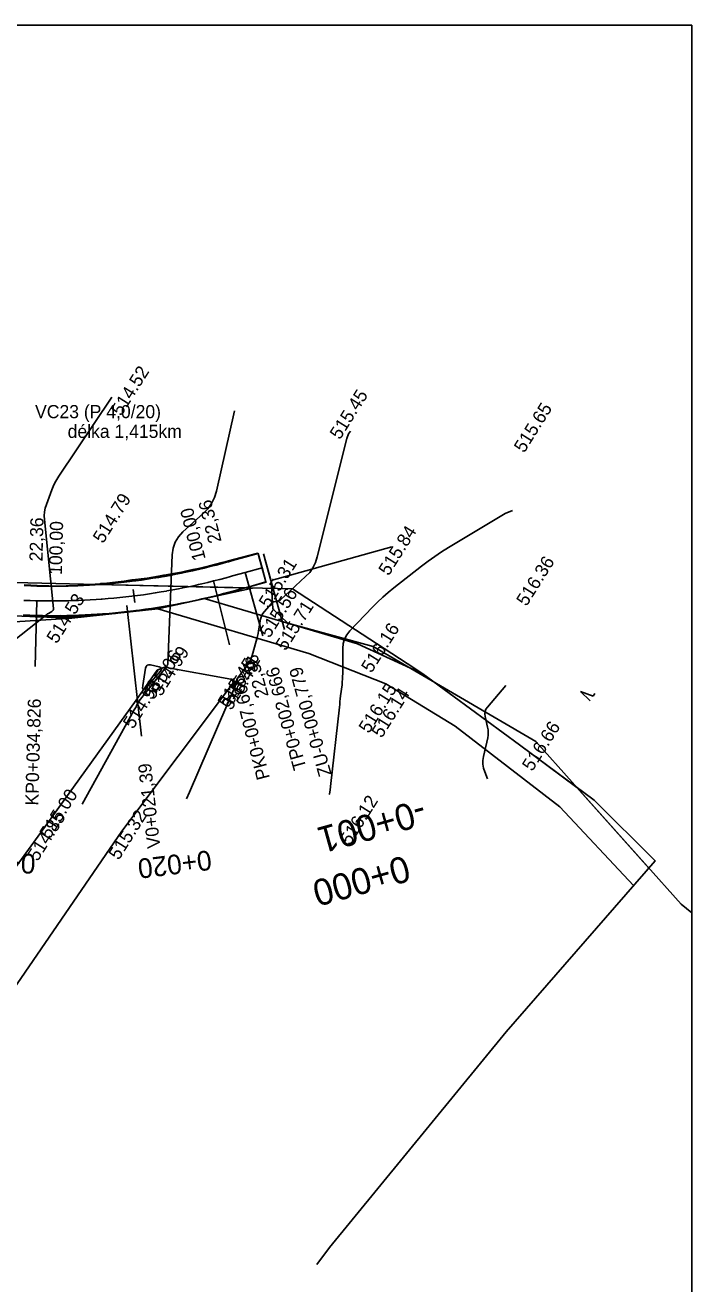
# Model space of a CAD drawing. Extents: x -636600 to -628587, y -1090963 to -1085869.
# Drawn here: x -629108.8 to -629007.3, y -1090119.5 to -1089927.9 of the extents above; entities that cross this region are included whole.
import ezdxf

# ---------------------------------------------------------------- set-up
doc = ezdxf.new("R2010")
doc.units = 0
for name, color, linetype in [('01_OBVOD PÚ', 7, 'Continuous'), ('01_PARCELY_NÁVRH_PC', 7, 'Continuous'), ('08_LEGENDA_HV', 7, 'Continuous'), ('42', 7, 'Continuous'), ('43', 7, 'Continuous'), ('Ex_Major Contours', 7, 'Continuous'), ('Ex_Minor Contours', 7, 'Continuous'), ('HEKTOMETRY100', 7, 'Continuous'), ('HEKTOMETRY20', 7, 'Continuous'), ('HL_BODY', 7, 'Continuous'), ('koty_vše', 7, 'Continuous'), ('POLOMERY', 7, 'Continuous'), ('popis', 7, 'Continuous'), ('situace_osa', 7, 'Continuous'), ('situace_těleso', 7, 'Continuous'), ('situace_vozovka', 7, 'Continuous'), ('VRCHOLY', 7, 'Continuous')]:
    doc.layers.add(name, color=color, linetype=linetype)

msp = doc.modelspace()

# ---------------------------------------------------------------- linework, layer by layer
at = {"layer": '01_OBVOD PÚ'}
msp.add_lwpolyline([(-629064.38, -1090116.55), (-629062.45, -1090113.97), (-629035.57, -1090081.14), (-629012.84, -1090055.12), (-629022.13, -1090045.89), (-629033.54, -1090037.48), (-629043.49, -1090030.13), (-629048.22, -1090026.65), (-629050.62, -1090025.1), (-629055.31, -1090022.04), (-629068.09, -1090013.73), (-629099.9, -1090012.99), (-629131.7, -1090012.25), (-629148.72, -1090013.61), (-629154.84, -1090014.09), (-629280.62, -1090038.37), (-629307.14, -1090043.49), (-629296.45, -1090016.73), (-629293.93, -1090012.42), (-629270.46, -1089972.35), (-629268.57, -1089963.42), (-629266.63, -1089954.23), (-629265, -1089934.28), (-629263.49, -1089927.9)], dxfattribs=at)
at = {"layer": '01_PARCELY_NÁVRH_PC'}
for points in [[(-629423.86, -1090066.33), (-629301.32, -1090047.36), (-629158.55, -1090019.65), (-629143.13, -1090017.81), (-629127.19, -1090017.17), (-629101.71, -1090018.17), (-629088.61, -1090016.74), (-629074.2, -1090013.59), (-629099.9, -1090012.99), (-629131.7, -1090012.25), (-629148.72, -1090013.61), (-629154.84, -1090014.09), (-629280.62, -1090038.37), (-629307.14, -1090043.49), (-629404.13, -1090058.24), (-629408.64, -1090057.19), (-629412.28, -1090054.2), (-629414.18, -1090049.97)], [(-629088.61, -1090016.74), (-629065.6, -1090023.54), (-629053.87, -1090028.16), (-629043.32, -1090034.61), (-629027.38, -1090046.89), (-629016.13, -1090058.88), (-629013.81, -1090056.23), (-629024.77, -1090043.95), (-629033.54, -1090037.48), (-629043.49, -1090030.13), (-629048.22, -1090026.65), (-629058.17, -1090022.09), (-629081.52, -1090015.19)], [(-629422, -1090069.08), (-629420.02, -1090065.73), (-629301.32, -1090047.36), (-629158.55, -1090019.65), (-629143.13, -1090017.81), (-629127.19, -1090017.17), (-629101.71, -1090018.17), (-629142.89, -1090020.81), (-629158.08, -1090022.61), (-629300.81, -1090050.32)]]:
    msp.add_lwpolyline(points, close=True, dxfattribs=at)
at = {"layer": '08_LEGENDA_HV'}
for p, q in [((-629847.27, -1089927.9), (-629007.27, -1089927.9)), ((-629007.27, -1089927.9), (-629007.27, -1090224.9))]:
    msp.add_line(p, q, dxfattribs=at)
at = {"layer": '42'}
for p, q in [((-629052.97, -1090007.33), (-629071.33, -1090012.46)), ((-629071.33, -1090012.46), (-629071.08, -1090016.75)), ((-629071.08, -1090016.75), (-629068.78, -1090018.95)), ((-629068.78, -1090018.95), (-629055.83, -1090022.51)), ((-629055.83, -1090022.51), (-629031.01, -1090036.95)), ((-629091.88, -1090030.64), (-629088.68, -1090026.1)), ((-629088.68, -1090026.1), (-629087.6, -1090025.66)), ((-629087.6, -1090025.66), (-629077.47, -1090027.44)), ((-629076.93, -1090027.79), (-629094.07, -1090050.6)), ((-629077.47, -1090027.44), (-629076.93, -1090027.79)), ((-629106.43, -1090050.8), (-629091.88, -1090030.64)), ((-629031.01, -1090036.95), (-629008.9, -1090061.72)), ((-629094.07, -1090050.6), (-629117.95, -1090085.35)), ((-629115.01, -1090062.63), (-629106.43, -1090050.8)), ((-629008.9, -1090061.72), (-629007.27, -1090063.04))]:
    msp.add_line(p, q, dxfattribs=at)
at = {"layer": '43'}
for p, q in [((-629022.75, -1090030.75), (-629024.23, -1090029.35)), ((-629024.23, -1090029.35), (-629022.32, -1090030.07)), ((-629022.32, -1090030.07), (-629022.05, -1090029.65))]:
    msp.add_line(p, q, dxfattribs=at)
at = {"layer": 'Ex_Major Contours'}
msp.add_lwpolyline([(-629076.95, -1089986.62), (-629079.68, -1089998.82), (-629079.98, -1089999.8), (-629080.41, -1090000.7), (-629080.98, -1090001.52), (-629081.69, -1090002.25), (-629084.79, -1090005.05), (-629085.47, -1090005.79), (-629085.98, -1090006.62), (-629086.29, -1090007.53), (-629086.43, -1090008.53), (-629087.09, -1090025.17), (-629087.1, -1090025.21), (-629087.11, -1090025.25), (-629087.13, -1090025.28), (-629087.15, -1090025.31), (-629087.28, -1090025.47), (-629087.3, -1090025.49), (-629087.31, -1090025.51), (-629087.32, -1090025.53), (-629087.32, -1090025.56), (-629087.35, -1090025.69), (-629087.35, -1090025.69), (-629087.35, -1090025.7), (-629087.35, -1090025.7), (-629087.36, -1090025.7), (-629087.37, -1090025.7), (-629087.38, -1090025.7), (-629087.38, -1090025.7), (-629087.39, -1090025.71), (-629087.39, -1090025.71), (-629091.26, -1090030.5), (-629091.27, -1090030.5), (-629091.27, -1090030.51), (-629091.29, -1090030.52), (-629091.29, -1090030.53), (-629091.29, -1090030.53), (-629091.29, -1090030.53), (-629091.3, -1090030.54), (-629091.83, -1090031.49), (-629091.92, -1090031.65), (-629092.01, -1090031.82), (-629092.1, -1090031.98), (-629092.19, -1090032.14), (-629100.14, -1090046.49)], dxfattribs=at)
msp.add_lwpolyline([(-629090.22, -1090025.35), (-629089.99, -1090025.27), (-629089.7, -1090025.29), (-629088.41, -1090025.58), (-629088.15, -1090025.68), (-629088.03, -1090025.81), (-629088.04, -1090026), (-629088.2, -1090026.22), (-629090.35, -1090028.68), (-629090.66, -1090028.97), (-629090.85, -1090029.03), (-629090.93, -1090028.84), (-629090.9, -1090028.42), (-629090.46, -1090025.8), (-629090.37, -1090025.52)], close=True, dxfattribs=at)
at = {"layer": 'Ex_Minor Contours'}
for points in [[(-629115.79, -1090025.74), (-629105.77, -1090017.8), (-629105.65, -1090017.7), (-629105.52, -1090017.62), (-629105.39, -1090017.53), (-629105.26, -1090017.46), (-629104.73, -1090017.16), (-629104.62, -1090017.07), (-629104.54, -1090016.97), (-629104.5, -1090016.84), (-629104.5, -1090016.7), (-629105.87, -1090003.17), (-629105.89, -1090002.58), (-629105.85, -1090002.01), (-629105.75, -1090001.44), (-629105.58, -1090000.88), (-629104.76, -1089998.66), (-629104.54, -1089998.11), (-629104.29, -1089997.58), (-629104.01, -1089997.06), (-629103.69, -1089996.56), (-629095.62, -1089984.55)], [(-629084.26, -1090045.69), (-629083.78, -1090044.67), (-629076.67, -1090028.19), (-629076.66, -1090028.16), (-629076.65, -1090028.13), (-629076.64, -1090028.09), (-629076.64, -1090028.06), (-629076.62, -1090027.92), (-629076.62, -1090027.89), (-629076.61, -1090027.85), (-629076.61, -1090027.82), (-629076.61, -1090027.78), (-629076.57, -1090027.51), (-629076.56, -1090027.45), (-629076.54, -1090027.4), (-629076.52, -1090027.35), (-629076.49, -1090027.3), (-629074.99, -1090025.37), (-629074.75, -1090025.02), (-629074.54, -1090024.66), (-629074.37, -1090024.28), (-629074.24, -1090023.87), (-629073.63, -1090021.7), (-629073.53, -1090021.31), (-629073.43, -1090020.91), (-629073.34, -1090020.51), (-629073.26, -1090020.11), (-629072.94, -1090018.32), (-629072.86, -1090018.02), (-629072.75, -1090017.72), (-629072.59, -1090017.45), (-629072.4, -1090017.2), (-629071.31, -1090015.92), (-629071.22, -1090015.83), (-629071.12, -1090015.76), (-629071.01, -1090015.71), (-629070.89, -1090015.68), (-629070.37, -1090015.59), (-629070.25, -1090015.56), (-629070.13, -1090015.51), (-629070.03, -1090015.45), (-629069.93, -1090015.37), (-629066.09, -1090011.85), (-629065.47, -1090011.2), (-629064.97, -1090010.49), (-629064.58, -1090009.7), (-629064.31, -1090008.85), (-629059.83, -1089990.81), (-629059.56, -1089990.09), (-629059.28, -1089989.68)], [(-629034.58, -1090001.76), (-629035.7, -1090002.24), (-629044.31, -1090007.43), (-629045.38, -1090008.1), (-629046.42, -1090008.79), (-629047.45, -1090009.52), (-629048.45, -1090010.28), (-629052.68, -1090013.58), (-629053.52, -1090014.26), (-629054.35, -1090014.98), (-629055.14, -1090015.73), (-629055.91, -1090016.5), (-629059.36, -1090020.12), (-629059.83, -1090020.71), (-629060.17, -1090021.35), (-629060.37, -1090022.05), (-629060.44, -1090022.8), (-629060.45, -1090026.61), (-629060.46, -1090027.04), (-629060.48, -1090027.47), (-629060.51, -1090027.89), (-629060.55, -1090028.32), (-629060.76, -1090030.02), (-629060.81, -1090030.45), (-629060.86, -1090030.87), (-629060.9, -1090031.3), (-629060.95, -1090031.73), (-629062.28, -1090043.81), (-629062.36, -1090044.37), (-629062.48, -1090044.91), (-629062.52, -1090045.04)], [(-629035.58, -1090028.42), (-629038.41, -1090031.7), (-629038.63, -1090032.03), (-629038.77, -1090032.38), (-629038.81, -1090032.75), (-629038.76, -1090033.14), (-629038.37, -1090034.76), (-629038.29, -1090035.16), (-629038.27, -1090035.57), (-629038.29, -1090035.98), (-629038.36, -1090036.38), (-629038.99, -1090039.21), (-629039.08, -1090039.82), (-629039.08, -1090040.42), (-629038.99, -1090041.01), (-629038.82, -1090041.59), (-629038.4, -1090042.66)]]:
    msp.add_lwpolyline(points, dxfattribs=at)
at = {"layer": 'HEKTOMETRY100'}
for points in [[(-629072.19, -1090012.42), (-629073.27, -1090008.57)], [(-629071.44, -1090012.21), (-629072.52, -1090008.36)]]:
    msp.add_lwpolyline(points, dxfattribs=at)
at = {"layer": 'HEKTOMETRY20'}
for points in [[(-629071.71, -1090011.25), (-629072.25, -1090009.32)], [(-629092.12, -1090015.78), (-629092.36, -1090013.8)]]:
    msp.add_lwpolyline(points, dxfattribs=at)
at = {"layer": 'HL_BODY'}
for points in [[(-629071.98, -1090010.28), (-629069.29, -1090019.92)], [(-629080.13, -1090012.51), (-629077.68, -1090022.21)], [(-629075.3, -1090011.21), (-629072.61, -1090020.84)], [(-629107.03, -1090015.52), (-629107.28, -1090025.52)]]:
    msp.add_lwpolyline(points, dxfattribs=at)
at = {"layer": 'POLOMERY'}
for points in [[(-629071.98, -1090010.28), (-629069.29, -1090019.92)], [(-629080.13, -1090012.51), (-629077.68, -1090022.21)], [(-629075.3, -1090011.21), (-629072.61, -1090020.84)], [(-629107.03, -1090015.52), (-629107.28, -1090025.52)]]:
    msp.add_lwpolyline(points, dxfattribs=at)
at = {"layer": 'situace_osa'}
msp.add_lwpolyline([(-629072.73, -1090010.49), (-629075.3, -1090011.21), (-629076.26, -1090011.48), (-629077.23, -1090011.75), (-629077.55, -1090011.83), (-629078.19, -1090012.01), (-629079.16, -1090012.27), (-629080.13, -1090012.51), (-629081.01, -1090012.73), (-629081.89, -1090012.94), (-629082.4, -1090013.06), (-629082.77, -1090013.14), (-629083.65, -1090013.34), (-629084.54, -1090013.52), (-629085.43, -1090013.7), (-629086.32, -1090013.87), (-629087.21, -1090014.03), (-629087.3, -1090014.05), (-629088.1, -1090014.18), (-629088.99, -1090014.33), (-629089.89, -1090014.47), (-629090.78, -1090014.6), (-629091.68, -1090014.72), (-629092.24, -1090014.79), (-629092.58, -1090014.83), (-629093.48, -1090014.93), (-629094.38, -1090015.03), (-629095.28, -1090015.12), (-629096.18, -1090015.2), (-629097.08, -1090015.27), (-629097.22, -1090015.28), (-629097.99, -1090015.34), (-629098.89, -1090015.39), (-629099.79, -1090015.44), (-629100.7, -1090015.48), (-629101.6, -1090015.51), (-629102.21, -1090015.53), (-629102.51, -1090015.53), (-629103.41, -1090015.55), (-629104.32, -1090015.55), (-629105.22, -1090015.55), (-629106.13, -1090015.54), (-629107.03, -1090015.52), (-629107.21, -1090015.52), (-629108.03, -1090015.5), (-629109.03, -1090015.46)], dxfattribs=at)
at = {"layer": 'situace_těleso'}
msp.add_lwpolyline([(-629109.13, -1090017.87), (-629108.12, -1090017.92), (-629107.27, -1090017.96), (-629107.09, -1090017.96), (-629106.17, -1090017.99), (-629105.24, -1090018.02), (-629104.31, -1090018.03), (-629103.38, -1090018.04), (-629102.46, -1090018.02), (-629102.15, -1090018), (-629101.53, -1090017.97), (-629100.6, -1090017.92), (-629099.68, -1090017.86), (-629098.75, -1090017.8), (-629097.83, -1090017.72), (-629097.04, -1090017.65), (-629096.91, -1090017.64), (-629095.98, -1090017.54), (-629095.06, -1090017.44), (-629094.14, -1090017.33), (-629093.22, -1090017.22), (-629092.31, -1090017.09), (-629091.96, -1090017.04), (-629091.39, -1090016.96), (-629090.47, -1090016.82), (-629089.56, -1090016.69), (-629088.64, -1090016.55), (-629087.73, -1090016.41), (-629086.91, -1090016.27), (-629086.81, -1090016.25), (-629085.9, -1090016.09), (-629084.99, -1090015.92), (-629084.09, -1090015.74), (-629083.18, -1090015.55), (-629082.27, -1090015.35), (-629081.89, -1090015.27), (-629081.37, -1090015.15), (-629080.47, -1090014.94), (-629079.57, -1090014.72), (-629078.58, -1090014.46), (-629077.6, -1090014.21), (-629076.95, -1090014.03), (-629076.62, -1090013.94), (-629075.65, -1090013.68), (-629074.69, -1090013.41), (-629072.11, -1090012.7), (-629072.13, -1090012.66), (-629072.73, -1090010.49), (-629073.34, -1090008.33), (-629073.35, -1090008.28), (-629075.93, -1090008.96), (-629076.89, -1090009.21), (-629077.86, -1090009.45), (-629078.18, -1090009.53), (-629078.81, -1090009.7), (-629079.77, -1090009.95), (-629080.71, -1090010.19), (-629081.57, -1090010.39), (-629082.43, -1090010.6), (-629082.93, -1090010.71), (-629083.29, -1090010.79), (-629084.16, -1090010.97), (-629085.02, -1090011.15), (-629085.89, -1090011.32), (-629086.76, -1090011.48), (-629087.63, -1090011.64), (-629087.72, -1090011.65), (-629088.5, -1090011.79), (-629089.37, -1090011.92), (-629090.25, -1090012.06), (-629091.12, -1090012.18), (-629092, -1090012.29), (-629092.54, -1090012.36), (-629092.87, -1090012.41), (-629093.75, -1090012.52), (-629094.62, -1090012.63), (-629095.5, -1090012.74), (-629096.38, -1090012.83), (-629097.26, -1090012.92), (-629097.39, -1090012.93), (-629098.14, -1090013), (-629099.02, -1090013.07), (-629099.91, -1090013.13), (-629100.79, -1090013.18), (-629101.67, -1090013.23), (-629102.26, -1090013.26), (-629102.56, -1090013.27), (-629103.44, -1090013.3), (-629104.33, -1090013.29), (-629105.21, -1090013.27), (-629106.09, -1090013.24), (-629106.98, -1090013.21), (-629107.15, -1090013.2), (-629107.96, -1090013.16), (-629108.94, -1090013.11)], dxfattribs=at)
at = {"layer": 'situace_vozovka'}
for points in [[(-629073.34, -1090008.33), (-629075.9, -1090009.04), (-629076.87, -1090009.31), (-629077.82, -1090009.58), (-629078.14, -1090009.66), (-629078.78, -1090009.84), (-629079.73, -1090010.09), (-629080.68, -1090010.33), (-629081.54, -1090010.55), (-629082.4, -1090010.75), (-629082.89, -1090010.87), (-629083.26, -1090010.95), (-629084.12, -1090011.14), (-629084.99, -1090011.32), (-629085.86, -1090011.49), (-629086.73, -1090011.66), (-629087.6, -1090011.82), (-629087.69, -1090011.83), (-629088.47, -1090011.97), (-629089.34, -1090012.11), (-629090.22, -1090012.24), (-629091.09, -1090012.37), (-629091.97, -1090012.49), (-629092.52, -1090012.56), (-629092.85, -1090012.6), (-629093.73, -1090012.7), (-629094.61, -1090012.79), (-629095.49, -1090012.88), (-629096.37, -1090012.96), (-629097.25, -1090013.03), (-629097.38, -1090013.04), (-629098.14, -1090013.09), (-629099.02, -1090013.15), (-629099.9, -1090013.19), (-629100.79, -1090013.23), (-629101.67, -1090013.26), (-629102.26, -1090013.28), (-629102.56, -1090013.28), (-629103.44, -1090013.3), (-629104.33, -1090013.3), (-629105.21, -1090013.3), (-629106.09, -1090013.29), (-629106.98, -1090013.28), (-629107.15, -1090013.27), (-629107.96, -1090013.25), (-629108.94, -1090013.21)], [(-629072.13, -1090012.66), (-629074.69, -1090013.38), (-629075.66, -1090013.65), (-629076.63, -1090013.92), (-629076.96, -1090014), (-629077.61, -1090014.18), (-629078.59, -1090014.44), (-629079.58, -1090014.7), (-629080.47, -1090014.92), (-629081.37, -1090015.13), (-629081.9, -1090015.25), (-629082.28, -1090015.34), (-629083.18, -1090015.54), (-629084.09, -1090015.73), (-629085, -1090015.91), (-629085.9, -1090016.08), (-629086.82, -1090016.25), (-629086.91, -1090016.26), (-629087.73, -1090016.4), (-629088.64, -1090016.55), (-629089.56, -1090016.69), (-629090.47, -1090016.82), (-629091.39, -1090016.95), (-629091.96, -1090017.02), (-629092.31, -1090017.06), (-629093.23, -1090017.17), (-629094.15, -1090017.27), (-629095.07, -1090017.36), (-629095.99, -1090017.44), (-629096.91, -1090017.52), (-629097.05, -1090017.53), (-629097.84, -1090017.58), (-629098.76, -1090017.64), (-629099.69, -1090017.69), (-629100.61, -1090017.73), (-629101.54, -1090017.76), (-629102.16, -1090017.78), (-629102.46, -1090017.78), (-629103.39, -1090017.8), (-629104.31, -1090017.8), (-629105.24, -1090017.8), (-629106.16, -1090017.79), (-629107.09, -1090017.77), (-629107.27, -1090017.77), (-629108.11, -1090017.74), (-629109.12, -1090017.71)]]:
    msp.add_lwpolyline(points, dxfattribs=at)
at = {"layer": 'VRCHOLY'}
msp.add_lwpolyline([(-629093.33, -1090016.24), (-629091.11, -1090036.12)], dxfattribs=at)

# ---------------------------------------------------------------- texts
at = {"layer": 'HEKTOMETRY100'}
for s, p in [('-0+001', (-629048.39, -1090045.64)), ('0+000', (-629050.89, -1090054.23))]:
    msp.add_text(s, height=4, rotation=195.5956, dxfattribs=at).set_placement(p)
at = {"layer": 'HEKTOMETRY20'}
for s, rotation, p in [('0+040', 177.1696, (-629107.16, -1090054.11)), ('0+020', 187.0966, (-629080.62, -1090053.48))]:
    msp.add_text(s, height=3, rotation=rotation, dxfattribs=at).set_placement(p)
at = {"layer": 'HL_BODY'}
for s, rotation, p in [('TP0+002,666', 105.5956, (-629065.95, -1090040.97)), ('ZU-0+000,779', 105.5956, (-629062.1, -1090041.96)), ('PK0+007,666', 104.1632, (-629071.53, -1090042.5)), ('KP0+034,826', 88.602, (-629106.8, -1090046.72))]:
    msp.add_text(s, height=2, rotation=rotation, dxfattribs=at).set_placement(p)
at = {"layer": 'koty_vše'}
for s, p in [('514.52', (-629094.18, -1089987.52)), ('515.45', (-629060.87, -1089991.11)), ('515.65', (-629032.81, -1089993.13)), ('514.79', (-629096.95, -1090006.92)), ('515.84', (-629053.45, -1090011.84)), ('515.31', (-629071.68, -1090016.78)), ('516.36', (-629032.45, -1090016.48)), ('514.53', (-629104, -1090022.18)), ('515.56', (-629071.59, -1090021.31)), ('515.71', (-629069.13, -1090023.27)), ('516.16', (-629056.07, -1090026.64)), ('514.99', (-629088.09, -1090030.19)), ('515.06', (-629089.23, -1090030.73)), ('515.45', (-629077.94, -1090031.96)), ('515.41', (-629077.26, -1090031.47)), ('515.49', (-629077.41, -1090032.32)), ('514.98', (-629092.36, -1090035.17)), ('516.15', (-629056.46, -1090035.84)), ('516.14', (-629054.5, -1090036.54)), ('516.66', (-629031.57, -1090041.61)), ('515.00', (-629105.08, -1090051.92)), ('516.12', (-629059.33, -1090052.88)), ('514.85', (-629106.91, -1090055.31)), ('515.32', (-629094.55, -1090055.12))]:
    msp.add_text(s, height=2, rotation=57.8371, dxfattribs=at).set_placement(p)
at = {"layer": 'POLOMERY'}
for s, rotation, p in [('100,00', 104.1632, (-629081.3, -1090009.14)), ('22,36', 104.1632, (-629078.88, -1090006.48)), ('22,36', 88.602, (-629106.17, -1090009.55)), ('100,00', 88.602, (-629103.22, -1090011.6)), ('22,36', 105.5956, (-629071.7, -1090030))]:
    msp.add_text(s, height=2, rotation=rotation, dxfattribs=at).set_placement(p)
at = {"layer": 'popis'}
for s, p in [('VC23 (P 4,0/20)', (-629107.3, -1089987.73)), ('délka 1,415km', (-629102.34, -1089990.73))]:
    msp.add_text(s, height=2, dxfattribs=at).set_placement(p)
at = {"layer": 'VRCHOLY'}
msp.add_text('V0+021,39', height=2, rotation=96.3826, dxfattribs=at).set_placement((-629088.2, -1090053.11))

doc.saveas('drawing.dxf')
